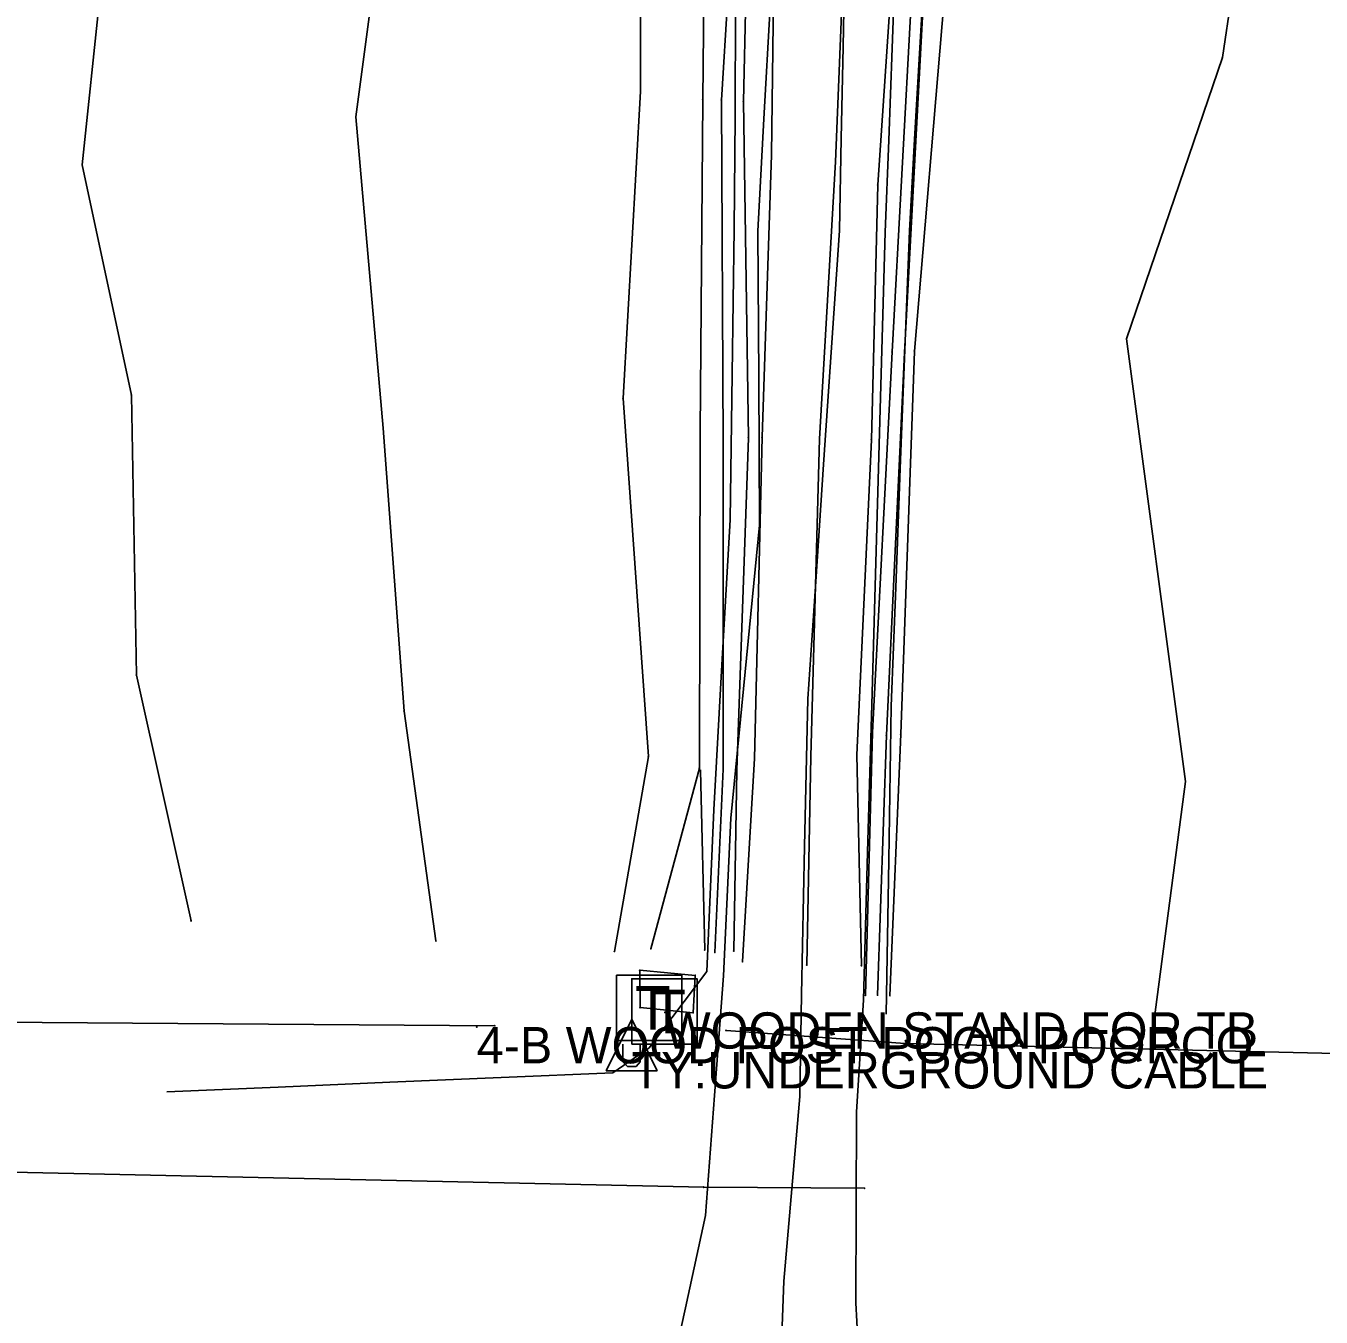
# Model space of a CAD drawing. Extents: x 976456 to 985170, y 1525951 to 1527080.
# Drawn here: x 978253.9 to 978432.3, y 1526540.8 to 1526718.6 of the extents above; entities that cross this region are included whole.
import ezdxf

# ---------------------------------------------------------------- set-up
doc = ezdxf.new("R2010")
doc.units = 0
for name, color, linetype in [('S_BREAKLINE', 7, 'Continuous'), ('S_DITCHLINE', 7, 'Continuous'), ('S_FENCE', 7, 'Continuous'), ('S_FIBER_OPTIC_CABLE', 7, 'Continuous'), ('S_GRAVEL_ROAD', 7, 'Continuous'), ('S_GRD_PT_SYM', 7, 'Continuous'), ('S_MISC_STRUCTURES', 7, 'Continuous'), ('S_MSC_PT_SYM', 7, 'Continuous'), ('S_PAVEMENT_CROWN', 7, 'Continuous'), ('S_RDW_PT_SYM', 7, 'Continuous'), ('S_SURVEY_TEXT_ANNOT', 7, 'Continuous'), ('S_TELEPHONE_UTILITIES', 7, 'Continuous'), ('S_UNDERGROUND_CABLE', 7, 'Continuous'), ('S_UTILITY_POLE_ANNOT', 7, 'Continuous'), ('S_UTL_PT_SYM', 7, 'Continuous')]:
    doc.layers.add(name, color=color, linetype=linetype)

msp = doc.modelspace()

# ---------------------------------------------------------------- linework, layer by layer
at = {"layer": 'S_BREAKLINE'}
for p, q in [((978418.68, 1526714.25), (978425.55, 1526759.95)), ((978261.62, 1526699.5), (978266.24, 1526744)), ((978347.1, 1526708.43), (978347.36, 1526737.43)), ((978338.52, 1526709.56), (978338.52, 1526735.78)), ((978299.32, 1526706.1), (978302.57, 1526730.84)), ((978376.24, 1526673.84), (978380.33, 1526722.25)), ((978405.48, 1526675.5), (978418.68, 1526714.25)), ((978336.11, 1526667.34), (978338.52, 1526709.56)), ((978346.75, 1526662.72), (978347.1, 1526708.43)), ((978303.08, 1526663.24), (978299.32, 1526706.1)), ((978268.38, 1526667.77), (978261.62, 1526699.5)), ((978374.37, 1526621.08), (978376.24, 1526673.84)), ((978413.6, 1526614.59), (978405.48, 1526675.5)), ((978269.07, 1526629.22), (978268.38, 1526667.77)), ((978339.61, 1526618.02), (978336.11, 1526667.34)), ((978305.96, 1526624.28), (978303.08, 1526663.24)), ((978346.63, 1526616.43), (978346.75, 1526662.72)), ((978276.61, 1526595.39), (978269.07, 1526629.22)), ((978310.34, 1526592.62), (978305.96, 1526624.28)), ((978372.87, 1526585.11), (978374.37, 1526621.08)), ((978334.92, 1526591.19), (978339.61, 1526618.02)), ((978339.95, 1526591.55), (978346.63, 1526616.43)), ((978347.37, 1526591.38), (978346.77, 1526616.11)), ((978408.82, 1526578.25), (978413.6, 1526614.59))]:
    msp.add_line(p, q, dxfattribs=at)
at = {"layer": 'S_DITCHLINE'}
for p, q in [((978352.68, 1526708.2), (978353.45, 1526738.65)), ((978349.66, 1526708.4), (978351.5, 1526737.72)), ((978373.17, 1526673.71), (978375.84, 1526722.59)), ((978374.89, 1526673.66), (978377.5, 1526722.48)), ((978349.91, 1526661.21), (978349.66, 1526708.4)), ((978353.37, 1526661.91), (978352.68, 1526708.2)), ((978370.48, 1526621.32), (978373.17, 1526673.71)), ((978372.39, 1526620.95), (978374.89, 1526673.66)), ((978351.78, 1526616.14), (978353.37, 1526661.91)), ((978349.91, 1526616.25), (978349.91, 1526661.21)), ((978369.51, 1526585.14), (978370.48, 1526621.32)), ((978371.18, 1526585.16), (978372.39, 1526620.95)), ((978348.77, 1526591.04), (978349.91, 1526616.25)), ((978351.37, 1526591.22), (978351.78, 1526616.14))]:
    msp.add_line(p, q, dxfattribs=at)
for points in [[(978357.79, 1526856.67), (978354.22, 1526794.28), (978353.42, 1526780.26), (978352.61, 1526766.23), (978351.81, 1526752.21), (978351.72, 1526736.82), (978351.62, 1526721.44), (978351.53, 1526706.05), (978351.43, 1526690.66), (978351.15, 1526670.64), (978350.87, 1526650.61), (978349.73, 1526630.64), (978348.6, 1526610.67), (978347.67, 1526588.4), (978339.7, 1526577.91), (978334.68, 1526574.46), (978319.32, 1526573.81), (978303.97, 1526573.16), (978288.62, 1526572.51), (978273.26, 1526571.86)], [(978372.35, 1526582.55), (978372.7, 1526603.74), (978373.04, 1526624.94), (978373.67, 1526641.3), (978374.3, 1526657.67), (978374.93, 1526674.03), (978375.55, 1526690.4), (978376.27, 1526702.99), (978376.99, 1526715.58), (978377.71, 1526728.18), (978378.43, 1526740.77), (978379.31, 1526756.58), (978380.19, 1526772.4), (978381.08, 1526788.21), (978384.83, 1526855.41)]]:
    msp.add_lwpolyline(points, dxfattribs=at)
at = {"layer": 'S_FENCE'}
msp.add_line((978318.44, 1526580.95), (978247.82, 1526581.44), dxfattribs=at)
at = {"layer": 'S_FIBER_OPTIC_CABLE'}
for p, q in [((978374.97, 1526578.48), (978350.29, 1526580.3)), ((978494.25, 1526575.74), (978374.97, 1526578.48)), ((978347.23, 1526558.72), (978248.82, 1526560.85)), ((978369.38, 1526558.57), (978347.23, 1526558.72))]:
    msp.add_line(p, q, dxfattribs=at)
at = {"layer": 'S_GRAVEL_ROAD'}
for p, q in [((978356.93, 1526729.73), (978356.58, 1526700.86)), ((978373.23, 1526726.99), (978371.2, 1526696.72)), ((978356.58, 1526700.86), (978355.27, 1526661.97)), ((978371.2, 1526696.72), (978370.33, 1526661.63)), ((978355.27, 1526661.97), (978354.23, 1526617.76)), ((978370.33, 1526661.63), (978368.32, 1526618.23)), ((978354.23, 1526617.76), (978352.57, 1526589.77)), ((978368.32, 1526618.23), (978368.94, 1526589.2))]:
    msp.add_line(p, q, dxfattribs=at)
for points in [[(978361.37, 1526856.47), (978359.38, 1526794.04), (978358.93, 1526780.06), (978358.49, 1526766.07), (978358.04, 1526752.09), (978357.2, 1526736.65), (978356.36, 1526721.22), (978355.52, 1526705.79), (978354.68, 1526690.35), (978354.79, 1526670.11), (978354.9, 1526649.86), (978352.93, 1526629.69), (978350.96, 1526609.51), (978349.95, 1526587.81), (978348.71, 1526571.32), (978347.48, 1526554.83), (978344.69, 1526542.11), (978341.91, 1526529.4), (978336.32, 1526519.7), (978328.9, 1526510.25)], [(978381.06, 1526508.64), (978369.53, 1526517.1), (978368.86, 1526529.94), (978368.19, 1526542.79), (978368.22, 1526555.92), (978368.26, 1526569.05), (978369.23, 1526584.52), (978369.8, 1526604.85), (978370.36, 1526625.19), (978370.83, 1526641.45), (978371.3, 1526657.71), (978371.76, 1526673.97), (978372.23, 1526690.23), (978372.7, 1526702.89), (978373.18, 1526715.55), (978373.65, 1526728.21), (978374.13, 1526740.87), (978374.79, 1526756.83), (978375.46, 1526772.79), (978376.12, 1526788.75), (978378.92, 1526855.74)]]:
    msp.add_lwpolyline(points, dxfattribs=at)
at = {"layer": 'S_GRD_PT_SYM'}
for points in [[(978418.68, 1526714.25), (978418.68, 1526714.3), (978418.68, 1526714.25), (978418.63, 1526714.25), (978418.68, 1526714.25), (978418.68, 1526714.2), (978418.68, 1526714.25), (978418.73, 1526714.25)], [(978338.52, 1526709.56), (978338.52, 1526709.61), (978338.52, 1526709.56), (978338.47, 1526709.56), (978338.52, 1526709.56), (978338.52, 1526709.51), (978338.52, 1526709.56), (978338.57, 1526709.56)], [(978347.1, 1526708.43), (978347.1, 1526708.48), (978347.1, 1526708.43), (978347.05, 1526708.43), (978347.1, 1526708.43), (978347.1, 1526708.38), (978347.1, 1526708.43), (978347.15, 1526708.43)], [(978349.66, 1526708.4), (978349.66, 1526708.45), (978349.66, 1526708.4), (978349.61, 1526708.4), (978349.66, 1526708.4), (978349.66, 1526708.35), (978349.66, 1526708.4), (978349.71, 1526708.4)], [(978352.68, 1526708.2), (978352.68, 1526708.25), (978352.68, 1526708.2), (978352.63, 1526708.2), (978352.68, 1526708.2), (978352.68, 1526708.15), (978352.68, 1526708.2), (978352.73, 1526708.2)], [(978299.32, 1526706.1), (978299.32, 1526706.15), (978299.32, 1526706.1), (978299.27, 1526706.1), (978299.32, 1526706.1), (978299.32, 1526706.05), (978299.32, 1526706.1), (978299.37, 1526706.1)], [(978261.62, 1526699.5), (978261.62, 1526699.55), (978261.62, 1526699.5), (978261.57, 1526699.5), (978261.62, 1526699.5), (978261.62, 1526699.45), (978261.62, 1526699.5), (978261.67, 1526699.5)], [(978405.48, 1526675.5), (978405.48, 1526675.55), (978405.48, 1526675.5), (978405.43, 1526675.5), (978405.48, 1526675.5), (978405.48, 1526675.45), (978405.48, 1526675.5), (978405.53, 1526675.5)], [(978373.17, 1526673.71), (978373.17, 1526673.76), (978373.17, 1526673.71), (978373.12, 1526673.71), (978373.17, 1526673.71), (978373.17, 1526673.66), (978373.17, 1526673.71), (978373.22, 1526673.71)], [(978376.24, 1526673.84), (978376.24, 1526673.89), (978376.24, 1526673.84), (978376.19, 1526673.84), (978376.24, 1526673.84), (978376.24, 1526673.79), (978376.24, 1526673.84), (978376.29, 1526673.84)], [(978374.89, 1526673.66), (978374.89, 1526673.71), (978374.89, 1526673.66), (978374.84, 1526673.66), (978374.89, 1526673.66), (978374.89, 1526673.61), (978374.89, 1526673.66), (978374.94, 1526673.66)], [(978268.38, 1526667.77), (978268.38, 1526667.82), (978268.38, 1526667.77), (978268.33, 1526667.77), (978268.38, 1526667.77), (978268.38, 1526667.72), (978268.38, 1526667.77), (978268.43, 1526667.77)], [(978336.11, 1526667.34), (978336.11, 1526667.39), (978336.11, 1526667.34), (978336.06, 1526667.34), (978336.11, 1526667.34), (978336.11, 1526667.29), (978336.11, 1526667.34), (978336.16, 1526667.34)], [(978303.08, 1526663.24), (978303.08, 1526663.29), (978303.08, 1526663.24), (978303.03, 1526663.24), (978303.08, 1526663.24), (978303.08, 1526663.19), (978303.08, 1526663.24), (978303.13, 1526663.24)], [(978346.75, 1526662.72), (978346.75, 1526662.77), (978346.75, 1526662.72), (978346.7, 1526662.72), (978346.75, 1526662.72), (978346.75, 1526662.67), (978346.75, 1526662.72), (978346.8, 1526662.72)], [(978349.91, 1526661.21), (978349.91, 1526661.26), (978349.91, 1526661.21), (978349.86, 1526661.21), (978349.91, 1526661.21), (978349.91, 1526661.16), (978349.91, 1526661.21), (978349.96, 1526661.21)], [(978353.37, 1526661.91), (978353.37, 1526661.96), (978353.37, 1526661.91), (978353.32, 1526661.91), (978353.37, 1526661.91), (978353.37, 1526661.86), (978353.37, 1526661.91), (978353.42, 1526661.91)], [(978269.07, 1526629.22), (978269.07, 1526629.27), (978269.07, 1526629.22), (978269.02, 1526629.22), (978269.07, 1526629.22), (978269.07, 1526629.17), (978269.07, 1526629.22), (978269.12, 1526629.22)], [(978305.96, 1526624.28), (978305.96, 1526624.33), (978305.96, 1526624.28), (978305.91, 1526624.28), (978305.96, 1526624.28), (978305.96, 1526624.23), (978305.96, 1526624.28), (978306.01, 1526624.28)], [(978370.48, 1526621.32), (978370.48, 1526621.37), (978370.48, 1526621.32), (978370.43, 1526621.32), (978370.48, 1526621.32), (978370.48, 1526621.27), (978370.48, 1526621.32), (978370.53, 1526621.32)], [(978372.39, 1526620.95), (978372.39, 1526621), (978372.39, 1526620.95), (978372.34, 1526620.95), (978372.39, 1526620.95), (978372.39, 1526620.9), (978372.39, 1526620.95), (978372.44, 1526620.95)], [(978374.37, 1526621.08), (978374.37, 1526621.14), (978374.37, 1526621.08), (978374.32, 1526621.08), (978374.37, 1526621.08), (978374.37, 1526621.03), (978374.37, 1526621.08), (978374.42, 1526621.08)], [(978339.61, 1526618.02), (978339.61, 1526618.07), (978339.61, 1526618.02), (978339.56, 1526618.02), (978339.61, 1526618.02), (978339.61, 1526617.97), (978339.61, 1526618.02), (978339.66, 1526618.02)], [(978346.63, 1526616.43), (978346.63, 1526616.48), (978346.63, 1526616.43), (978346.58, 1526616.43), (978346.63, 1526616.43), (978346.63, 1526616.38), (978346.63, 1526616.43), (978346.68, 1526616.43)], [(978346.77, 1526616.11), (978346.77, 1526616.16), (978346.77, 1526616.11), (978346.72, 1526616.11), (978346.77, 1526616.11), (978346.77, 1526616.06), (978346.77, 1526616.11), (978346.82, 1526616.11)], [(978349.91, 1526616.25), (978349.91, 1526616.3), (978349.91, 1526616.25), (978349.86, 1526616.25), (978349.91, 1526616.25), (978349.91, 1526616.2), (978349.91, 1526616.25), (978349.96, 1526616.25)], [(978351.78, 1526616.14), (978351.78, 1526616.19), (978351.78, 1526616.14), (978351.73, 1526616.14), (978351.78, 1526616.14), (978351.78, 1526616.09), (978351.78, 1526616.14), (978351.83, 1526616.14)], [(978413.6, 1526614.59), (978413.6, 1526614.64), (978413.6, 1526614.59), (978413.55, 1526614.59), (978413.6, 1526614.59), (978413.6, 1526614.54), (978413.6, 1526614.59), (978413.65, 1526614.59)], [(978276.61, 1526595.39), (978276.61, 1526595.44), (978276.61, 1526595.39), (978276.56, 1526595.39), (978276.61, 1526595.39), (978276.61, 1526595.34), (978276.61, 1526595.39), (978276.66, 1526595.39)], [(978310.34, 1526592.62), (978310.34, 1526592.67), (978310.34, 1526592.62), (978310.29, 1526592.62), (978310.34, 1526592.62), (978310.34, 1526592.57), (978310.34, 1526592.62), (978310.39, 1526592.62)], [(978334.92, 1526591.19), (978334.92, 1526591.24), (978334.92, 1526591.19), (978334.87, 1526591.19), (978334.92, 1526591.19), (978334.92, 1526591.14), (978334.92, 1526591.19), (978334.97, 1526591.19)], [(978339.95, 1526591.55), (978339.95, 1526591.6), (978339.95, 1526591.55), (978339.9, 1526591.55), (978339.95, 1526591.55), (978339.95, 1526591.5), (978339.95, 1526591.55), (978340, 1526591.55)], [(978347.37, 1526591.38), (978347.37, 1526591.43), (978347.37, 1526591.38), (978347.32, 1526591.38), (978347.37, 1526591.38), (978347.37, 1526591.33), (978347.37, 1526591.38), (978347.42, 1526591.38)], [(978348.77, 1526591.04), (978348.77, 1526591.09), (978348.77, 1526591.04), (978348.72, 1526591.04), (978348.77, 1526591.04), (978348.77, 1526590.99), (978348.77, 1526591.04), (978348.82, 1526591.04)], [(978351.37, 1526591.22), (978351.37, 1526591.27), (978351.37, 1526591.22), (978351.32, 1526591.22), (978351.37, 1526591.22), (978351.37, 1526591.17), (978351.37, 1526591.22), (978351.42, 1526591.22)], [(978369.51, 1526585.14), (978369.51, 1526585.19), (978369.51, 1526585.14), (978369.46, 1526585.14), (978369.51, 1526585.14), (978369.51, 1526585.09), (978369.51, 1526585.14), (978369.56, 1526585.14)], [(978371.18, 1526585.16), (978371.18, 1526585.21), (978371.18, 1526585.16), (978371.13, 1526585.16), (978371.18, 1526585.16), (978371.18, 1526585.11), (978371.18, 1526585.16), (978371.23, 1526585.16)], [(978372.87, 1526585.11), (978372.87, 1526585.16), (978372.87, 1526585.11), (978372.82, 1526585.11), (978372.87, 1526585.11), (978372.87, 1526585.06), (978372.87, 1526585.11), (978372.92, 1526585.11)], [(978408.82, 1526578.25), (978408.82, 1526578.3), (978408.82, 1526578.25), (978408.77, 1526578.25), (978408.82, 1526578.25), (978408.82, 1526578.2), (978408.82, 1526578.25), (978408.87, 1526578.25)]]:
    msp.add_lwpolyline(points, dxfattribs=at)
at = {"layer": 'S_MISC_STRUCTURES'}
for p, q in [((978338.46, 1526583.44), (978338.42, 1526588.58)), ((978338.42, 1526588.58), (978346.05, 1526587.86)), ((978346.05, 1526587.86), (978345.78, 1526582.73)), ((978345.78, 1526582.73), (978338.46, 1526583.44))]:
    msp.add_line(p, q, dxfattribs=at)
at = {"layer": 'S_MSC_PT_SYM'}
for points in [[(978338.42, 1526588.58), (978338.42, 1526588.63), (978338.42, 1526588.58), (978338.37, 1526588.58), (978338.42, 1526588.58), (978338.42, 1526588.53), (978338.42, 1526588.58), (978338.47, 1526588.58)], [(978346.05, 1526587.86), (978346.05, 1526587.91), (978346.05, 1526587.86), (978346, 1526587.86), (978346.05, 1526587.86), (978346.05, 1526587.81), (978346.05, 1526587.86), (978346.1, 1526587.86)], [(978338.46, 1526583.44), (978338.46, 1526583.49), (978338.46, 1526583.44), (978338.41, 1526583.44), (978338.46, 1526583.44), (978338.46, 1526583.39), (978338.46, 1526583.44), (978338.51, 1526583.44)], [(978341.87, 1526582.79), (978341.87, 1526582.84), (978341.87, 1526582.79), (978341.82, 1526582.79), (978341.87, 1526582.79), (978341.87, 1526582.74), (978341.87, 1526582.79), (978341.92, 1526582.79)], [(978345.78, 1526582.73), (978345.78, 1526582.78), (978345.78, 1526582.73), (978345.73, 1526582.73), (978345.78, 1526582.73), (978345.78, 1526582.68), (978345.78, 1526582.73), (978345.83, 1526582.73)], [(978318.44, 1526580.95), (978318.44, 1526581), (978318.44, 1526580.95), (978318.39, 1526580.95), (978318.44, 1526580.95), (978318.44, 1526580.9), (978318.44, 1526580.95), (978318.49, 1526580.95)], [(978315.95, 1526580.77), (978315.95, 1526580.82), (978315.95, 1526580.77), (978315.9, 1526580.77), (978315.95, 1526580.77), (978315.95, 1526580.72), (978315.95, 1526580.77), (978316, 1526580.77)]]:
    msp.add_lwpolyline(points, dxfattribs=at)
at = {"layer": 'S_PAVEMENT_CROWN'}
for p, q in [((978366.45, 1526727.14), (978365.38, 1526699.89)), ((978365.38, 1526699.89), (978363.19, 1526661.77)), ((978363.19, 1526661.77), (978361.99, 1526618)), ((978361.99, 1526618), (978361.41, 1526589.29))]:
    msp.add_line(p, q, dxfattribs=at)
msp.add_lwpolyline([(978356.9, 1526508.47), (978357.57, 1526527.13), (978358.24, 1526545.8), (978359.35, 1526558.49), (978360.47, 1526571.19), (978360.67, 1526585.26), (978361.11, 1526605.62), (978361.56, 1526625.97), (978362.65, 1526642.09), (978363.74, 1526658.21), (978364.83, 1526674.33), (978365.92, 1526690.45), (978366.17, 1526703.09), (978366.42, 1526715.74), (978366.67, 1526728.38), (978366.92, 1526741.02), (978367.64, 1526757.28), (978368.35, 1526773.54), (978369.07, 1526789.8), (978369.78, 1526806.07)], dxfattribs=at)
at = {"layer": 'S_RDW_PT_SYM'}
for points in [[(978356.58, 1526700.86), (978356.58, 1526700.91), (978356.58, 1526700.86), (978356.53, 1526700.86), (978356.58, 1526700.86), (978356.58, 1526700.81), (978356.58, 1526700.86), (978356.63, 1526700.86)], [(978365.38, 1526699.89), (978365.38, 1526699.94), (978365.38, 1526699.89), (978365.33, 1526699.89), (978365.38, 1526699.89), (978365.38, 1526699.84), (978365.38, 1526699.89), (978365.43, 1526699.89)], [(978371.2, 1526696.72), (978371.2, 1526696.77), (978371.2, 1526696.72), (978371.15, 1526696.72), (978371.2, 1526696.72), (978371.2, 1526696.67), (978371.2, 1526696.72), (978371.25, 1526696.72)], [(978355.27, 1526661.97), (978355.27, 1526662.02), (978355.27, 1526661.97), (978355.22, 1526661.97), (978355.27, 1526661.97), (978355.27, 1526661.92), (978355.27, 1526661.97), (978355.32, 1526661.97)], [(978363.19, 1526661.77), (978363.19, 1526661.82), (978363.19, 1526661.77), (978363.14, 1526661.77), (978363.19, 1526661.77), (978363.19, 1526661.72), (978363.19, 1526661.77), (978363.24, 1526661.77)], [(978370.33, 1526661.63), (978370.33, 1526661.68), (978370.33, 1526661.63), (978370.28, 1526661.63), (978370.33, 1526661.63), (978370.33, 1526661.58), (978370.33, 1526661.63), (978370.38, 1526661.63)], [(978354.23, 1526617.76), (978354.23, 1526617.81), (978354.23, 1526617.76), (978354.18, 1526617.76), (978354.23, 1526617.76), (978354.23, 1526617.71), (978354.23, 1526617.76), (978354.28, 1526617.76)], [(978361.99, 1526618), (978361.99, 1526618.05), (978361.99, 1526618), (978361.94, 1526618), (978361.99, 1526618), (978361.99, 1526617.95), (978361.99, 1526618), (978362.04, 1526618)], [(978368.32, 1526618.23), (978368.32, 1526618.28), (978368.32, 1526618.23), (978368.27, 1526618.23), (978368.32, 1526618.23), (978368.32, 1526618.18), (978368.32, 1526618.23), (978368.37, 1526618.23)], [(978352.57, 1526589.77), (978352.57, 1526589.82), (978352.57, 1526589.77), (978352.52, 1526589.77), (978352.57, 1526589.77), (978352.57, 1526589.72), (978352.57, 1526589.77), (978352.62, 1526589.77)], [(978361.41, 1526589.29), (978361.41, 1526589.34), (978361.41, 1526589.29), (978361.36, 1526589.29), (978361.41, 1526589.29), (978361.41, 1526589.24), (978361.41, 1526589.29), (978361.46, 1526589.29)], [(978368.94, 1526589.2), (978368.94, 1526589.25), (978368.94, 1526589.2), (978368.89, 1526589.2), (978368.94, 1526589.2), (978368.94, 1526589.15), (978368.94, 1526589.2), (978368.99, 1526589.2)]]:
    msp.add_lwpolyline(points, dxfattribs=at)
at = {"layer": 'S_TELEPHONE_UTILITIES'}
for points in [[(978335.21, 1526578.9), (978335.21, 1526587.9), (978344.21, 1526587.9), (978344.21, 1526578.9)], [(978337.3, 1526578.42), (978337.3, 1526587.42), (978346.3, 1526587.42), (978346.3, 1526578.42)]]:
    msp.add_lwpolyline(points, close=True, dxfattribs=at)
at = {"layer": 'S_UNDERGROUND_CABLE'}
for p, q in [((978337.3, 1526581.84), (978333.78, 1526574.75)), ((978337.3, 1526581.84), (978340.79, 1526574.75)), ((978336.1, 1526575.99), (978336.1, 1526578.43)), ((978338.46, 1526578.43), (978338.46, 1526575.99)), ((978336.72, 1526575.33), (978336.1, 1526575.99)), ((978338.46, 1526575.99), (978337.92, 1526575.33)), ((978333.78, 1526574.75), (978340.79, 1526574.75)), ((978337.92, 1526575.33), (978336.72, 1526575.33))]:
    msp.add_line(p, q, dxfattribs=at)
at = {"layer": 'S_UTL_PT_SYM'}
for points in [[(978350.29, 1526580.3), (978350.29, 1526580.35), (978350.29, 1526580.3), (978350.24, 1526580.3), (978350.29, 1526580.3), (978350.29, 1526580.25), (978350.29, 1526580.3), (978350.34, 1526580.3)], [(978374.97, 1526578.48), (978374.97, 1526578.53), (978374.97, 1526578.48), (978374.92, 1526578.48), (978374.97, 1526578.48), (978374.97, 1526578.43), (978374.97, 1526578.48), (978375.02, 1526578.48)], [(978347.23, 1526558.72), (978347.23, 1526558.77), (978347.23, 1526558.72), (978347.18, 1526558.72), (978347.23, 1526558.72), (978347.23, 1526558.67), (978347.23, 1526558.72), (978347.28, 1526558.72)], [(978369.38, 1526558.57), (978369.38, 1526558.62), (978369.38, 1526558.57), (978369.33, 1526558.57), (978369.38, 1526558.57), (978369.38, 1526558.52), (978369.38, 1526558.57), (978369.43, 1526558.57)]]:
    msp.add_lwpolyline(points, dxfattribs=at)

# ---------------------------------------------------------------- texts
at = {"layer": 'S_SURVEY_TEXT_ANNOT'}
for s, p in [('WOODEN STAND FOR TB', (978341.87, 1526577.79)), ('4-B WOOD POST POOR POORCO', (978315.95, 1526575.77))]:
    msp.add_text(s, height=5, dxfattribs=at).set_placement(p)
at = {"layer": 'S_TELEPHONE_UTILITIES'}
for p in [(978337.78, 1526580.4), (978339.86, 1526579.92)]:
    msp.add_text('T', height=6, rotation=360, dxfattribs=at).set_placement(p)
at = {"layer": 'S_UTILITY_POLE_ANNOT'}
msp.add_text('TY:UNDERGROUND CABLE', height=5, dxfattribs=at).set_placement((978337.3, 1526572.31))

doc.saveas('drawing.dxf')
